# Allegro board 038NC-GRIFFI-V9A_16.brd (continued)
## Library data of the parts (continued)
BC1 BC3 BC5 BC7 BC11 BC13 = 100U-50-E-S-6.6X6.6: Tolerance: TOL; User Part Number: PNXXXXXXXXXX
BC2 BC4 BC6 BC8 BC10 BC12 = 47U-100-E-S10X10-NI: User Part Number: PNXXXXXXXXXX; Tolerance: TOL
BD1 BD2 = BD120-3.5A-S8-LA: User Part Number: PNXXXXXXXXXX; Tolerance: TOL
BR1-BR3 = 560-1-S6: User Part Number: PNXXXXXXXXXX; Tolerance: TOL
BR4 = 1K-1-S6: User Part Number: PNXXXXXXXXXX; Tolerance: TOL
C14 = 1U-16-X5R-S4-YA: User Part Number: PNXXXXXXXXXX; Tolerance: TOL
C84-C86 = 1U-16-X6S-S4-TY: User Part Number: PNXXXXXXXXXX; Tolerance: TOL
C87-C89 UNK1CS1 UNK1CS4 UNK1CS5 UNK1CS19-UNK1CS23 UNK1CS25-UNK1CS28 UNK2CS1 UNK2CS4 UNK2CS5 UNK2CS19-UNK2CS23 UNK2CS25-UNK2CS28 UNK3CS1 UNK3CS4 UNK3CS5 UNK3CS19-UNK3CS23 UNK3CS25-UNK3CS28 UNK4CS1 UNK4CS4 UNK4CS5 UNK4CS19-UNK4CS23 UNK4CS25-UNK4CS28 UNK5CS1 UNK5CS4 UNK5CS5 UNK5CS19-UNK5CS23 UNK5CS25-UNK5CS28 UNK6CS1 UNK6CS4 UNK6CS5 UNK6CS19-UNK6CS23 UNK6CS25-UNK6CS28 UNK7CS1 UNK7CS4 UNK7CS5 UNK7CS19-UNK7CS23 UNK7CS25-UNK7CS28 UNK8CS1 UNK8CS4 UNK8CS5 UNK8CS19-UNK8CS23 UNK8CS25-UNK8CS28 UNK9CS1 UNK9CS4 UNK9CS5 UNK9CS19-UNK9CS23 UNK9CS25-UNK9CS28 UNK10CS1 UNK10CS4 UNK10CS5 UNK10CS19-UNK10CS23 UNK10CS25-UNK10CS28 UNK11CS1 UNK11CS4 UNK11CS5 UNK11CS19-UNK11CS23 UNK11CS25-UNK11CS28 UNK12CS1 UNK12CS4 UNK12CS5 UNK12CS19-UNK12CS23 UNK12CS25-UNK12CS28 UNK13CS1 UNK13CS4 UNK13CS5 UNK13CS19-UNK13CS23 UNK13CS25-UNK13CS28 UNK14CS1 UNK14CS4 UNK14CS5 UNK14CS19-UNK14CS23 UNK14CS25-UNK14CS28 UNK15CS1 UNK15CS4 UNK15CS5 UNK15CS19-UNK15CS23 UNK15CS25-UNK15CS28 UNK16CS1 UNK16CS4 UNK16CS5 UNK16CS19-UNK16CS23 UNK16CS25-UNK16CS28 = 0.1U-10-X7R-S4-MU-1: User Part Number: PNXXXXXXXXXX; Tolerance: TOL
C90 = 100P-50-X8R-S4-KEMET: User Part Number: PNXXXXXXXXXX; Tolerance: TOL
C99-C101 = 10U-35-T-SC: Tolerance: TOL; User Part Number: PNXXXXXXXXXX
C102 C103 = 1U-25-X7R-S6-WA: User Part Number: PNXXXXXXXXXX; Tolerance: TOL
FD1-FD16 REG1_P3V3 REG1_P_5V REG1_P_10V SDUP5V1 SDUP15V1 T_+15V T_-15V T_RLY_5V T_USER_5V T_USER_12V T_USER_-5V TP_EEP_GND TP_EPP_SCLK TP_EPP_SCLK_DGND1 TP_EPP_SDA TP_EPP_SDA_DGND1 TP_EPP_VCC TP_EPP_VCC_DGND1 TP_REG1_P3V3 TP_REG1_P_5V_DGND TP_REG1_P_10V_DGND TP_SDUP5V1 TP_SDUP15V1 TP_USER_GND1 TP_USER_SCLK1 TP_USER_SCLK1_DGND1 TP_USER_SDA1 TP_USER_SDA1_DGND1 UNK1TP_AVSS2/TST UNK1TP_GPIO0-UNK1TP_GPIO4 UNK1TP_LED0-UNK1TP_LED2 UNK1TP_LSIN1_F UNK1TP_LSIN1_G UNK1TP_LSIN1_S UNK1TP_LSIN2/NCHGEN_F UNK1TP_LSIN2/NCHGEN_G UNK1TP_LSIN2/NCHGEN_S UNK1TP_LSOUT1_F UNK1TP_LSOUT1_G UNK1TP_LSOUT1_S UNK1TP_LSOUT2/SUSPEND1_G UNK1TP_LSOUT2/SUSPEND1_S UNK1TP_LSOUT2/SUSPEND_F UNK1TP_NCHG/ATB0_F UNK1TP_NCHG/ATB0_G UNK1TP_NCHG/ATB0_S UNK1TP_NPG/ATB1_F UNK1TP_NPG/ATB1_G UNK1TP_NPG/ATB1_S UNK1TP_NTC UNK1TP_REF_5V UNK1TP_SCL UNK1TP_SDA UNK1TP_SHPHLD_F UNK1TP_SHPHLD_S UNK1TP_SW_F UNK1TP_SW_S UNK1TP_VBAT_F UNK1TP_VBAT_S UNK1TP_VBUS_F UNK1TP_VBUS_S UNK1TP_VDDIO_F UNK1TP_VDDIO_S UNK1TP_VEST UNK1TP_VOUT_F UNK1TP_VOUT_S UNK1TP_VSYS_F UNK1TP_VSYS_S UNK2TP_AVSS2/TST UNK2TP_GPIO0-UNK2TP_GPIO4 UNK2TP_LED0-UNK2TP_LED2 UNK2TP_LSIN1_F UNK2TP_LSIN1_G UNK2TP_LSIN1_S UNK2TP_LSIN2/NCHGEN_F UNK2TP_LSIN2/NCHGEN_G UNK2TP_LSIN2/NCHGEN_S UNK2TP_LSOUT1_F UNK2TP_LSOUT1_G UNK2TP_LSOUT1_S UNK2TP_LSOUT2/SUSPEND1_G UNK2TP_LSOUT2/SUSPEND1_S UNK2TP_LSOUT2/SUSPEND_F UNK2TP_NCHG/ATB0_F UNK2TP_NCHG/ATB0_G UNK2TP_NCHG/ATB0_S UNK2TP_NPG/ATB1_F UNK2TP_NPG/ATB1_G UNK2TP_NPG/ATB1_S UNK2TP_NTC UNK2TP_REF_5V UNK2TP_SCL UNK2TP_SDA UNK2TP_SHPHLD_F UNK2TP_SHPHLD_S UNK2TP_SW_F UNK2TP_SW_S UNK2TP_VBAT_F UNK2TP_VBAT_S UNK2TP_VBUS_F UNK2TP_VBUS_S UNK2TP_VDDIO_F UNK2TP_VDDIO_S UNK2TP_VEST UNK2TP_VOUT_F UNK2TP_VOUT_S UNK2TP_VSYS_F UNK2TP_VSYS_S UNK3TP_AVSS2/TST UNK3TP_GPIO0-UNK3TP_GPIO4 UNK3TP_LED0-UNK3TP_LED2 UNK3TP_LSIN1_F UNK3TP_LSIN1_G UNK3TP_LSIN1_S UNK3TP_LSIN2/NCHGEN_F UNK3TP_LSIN2/NCHGEN_G UNK3TP_LSIN2/NCHGEN_S UNK3TP_LSOUT1_F UNK3TP_LSOUT1_G UNK3TP_LSOUT1_S UNK3TP_LSOUT2/SUSPEND1_G UNK3TP_LSOUT2/SUSPEND1_S UNK3TP_LSOUT2/SUSPEND_F UNK3TP_NCHG/ATB0_F UNK3TP_NCHG/ATB0_G UNK3TP_NCHG/ATB0_S UNK3TP_NPG/ATB1_F UNK3TP_NPG/ATB1_G UNK3TP_NPG/ATB1_S UNK3TP_NTC UNK3TP_REF_5V UNK3TP_SCL UNK3TP_SDA UNK3TP_SHPHLD_F UNK3TP_SHPHLD_S UNK3TP_SW_F UNK3TP_SW_S UNK3TP_VBAT_F UNK3TP_VBAT_S UNK3TP_VBUS_F UNK3TP_VBUS_S UNK3TP_VDDIO_F UNK3TP_VDDIO_S UNK3TP_VEST UNK3TP_VOUT_F UNK3TP_VOUT_S UNK3TP_VSYS_F UNK3TP_VSYS_S UNK4TP_AVSS2/TST UNK4TP_GPIO0-UNK4TP_GPIO4 UNK4TP_LED0-UNK4TP_LED2 UNK4TP_LSIN1_F UNK4TP_LSIN1_G UNK4TP_LSIN1_S UNK4TP_LSIN2/NCHGEN_F UNK4TP_LSIN2/NCHGEN_G UNK4TP_LSIN2/NCHGEN_S UNK4TP_LSOUT1_F UNK4TP_LSOUT1_G UNK4TP_LSOUT1_S UNK4TP_LSOUT2/SUSPEND1_G UNK4TP_LSOUT2/SUSPEND1_S UNK4TP_LSOUT2/SUSPEND_F UNK4TP_NCHG/ATB0_F UNK4TP_NCHG/ATB0_G UNK4TP_NCHG/ATB0_S UNK4TP_NPG/ATB1_F UNK4TP_NPG/ATB1_G UNK4TP_NPG/ATB1_S UNK4TP_NTC UNK4TP_REF_5V UNK4TP_SCL UNK4TP_SDA UNK4TP_SHPHLD_F UNK4TP_SHPHLD_S UNK4TP_SW_F UNK4TP_SW_S UNK4TP_VBAT_F UNK4TP_VBAT_S UNK4TP_VBUS_F UNK4TP_VBUS_S UNK4TP_VDDIO_F UNK4TP_VDDIO_S UNK4TP_VEST UNK4TP_VOUT_F UNK4TP_VOUT_S UNK4TP_VSYS_F UNK4TP_VSYS_S UNK5TP_AVSS2/TST UNK5TP_GPIO0-UNK5TP_GPIO4 UNK5TP_LED0-UNK5TP_LED2 UNK5TP_LSIN1_F UNK5TP_LSIN1_G UNK5TP_LSIN1_S UNK5TP_LSIN2/NCHGEN_F UNK5TP_LSIN2/NCHGEN_G UNK5TP_LSIN2/NCHGEN_S UNK5TP_LSOUT1_F UNK5TP_LSOUT1_G UNK5TP_LSOUT1_S UNK5TP_LSOUT2/SUSPEND1_G UNK5TP_LSOUT2/SUSPEND1_S UNK5TP_LSOUT2/SUSPEND_F UNK5TP_NCHG/ATB0_F UNK5TP_NCHG/ATB0_G UNK5TP_NCHG/ATB0_S UNK5TP_NPG/ATB1_F UNK5TP_NPG/ATB1_G UNK5TP_NPG/ATB1_S UNK5TP_NTC UNK5TP_REF_5V UNK5TP_SCL UNK5TP_SDA UNK5TP_SHPHLD_F UNK5TP_SHPHLD_S UNK5TP_SW_F UNK5TP_SW_S UNK5TP_VBAT_F UNK5TP_VBAT_S UNK5TP_VBUS_F UNK5TP_VBUS_S UNK5TP_VDDIO_F UNK5TP_VDDIO_S UNK5TP_VEST UNK5TP_VOUT_F UNK5TP_VOUT_S UNK5TP_VSYS_F UNK5TP_VSYS_S UNK6TP_AVSS2/TST UNK6TP_GPIO0-UNK6TP_GPIO4 UNK6TP_LED0-UNK6TP_LED2 UNK6TP_LSIN1_F UNK6TP_LSIN1_G UNK6TP_LSIN1_S UNK6TP_LSIN2/NCHGEN_F UNK6TP_LSIN2/NCHGEN_G UNK6TP_LSIN2/NCHGEN_S UNK6TP_LSOUT1_F UNK6TP_LSOUT1_G UNK6TP_LSOUT1_S UNK6TP_LSOUT2/SUSPEND1_G UNK6TP_LSOUT2/SUSPEND1_S UNK6TP_LSOUT2/SUSPEND_F UNK6TP_NCHG/ATB0_F UNK6TP_NCHG/ATB0_G UNK6TP_NCHG/ATB0_S UNK6TP_NPG/ATB1_F UNK6TP_NPG/ATB1_G UNK6TP_NPG/ATB1_S UNK6TP_NTC UNK6TP_REF_5V UNK6TP_SCL UNK6TP_SDA UNK6TP_SHPHLD_F UNK6TP_SHPHLD_S UNK6TP_SW_F UNK6TP_SW_S UNK6TP_VBAT_F UNK6TP_VBAT_S UNK6TP_VBUS_F UNK6TP_VBUS_S UNK6TP_VDDIO_F UNK6TP_VDDIO_S UNK6TP_VEST UNK6TP_VOUT_F UNK6TP_VOUT_S UNK6TP_VSYS_F UNK6TP_VSYS_S UNK7TP_AVSS2/TST UNK7TP_GPIO0-UNK7TP_GPIO4 UNK7TP_LED0-UNK7TP_LED2 UNK7TP_LSIN1_F UNK7TP_LSIN1_G UNK7TP_LSIN1_S UNK7TP_LSIN2/NCHGEN_F UNK7TP_LSIN2/NCHGEN_G UNK7TP_LSIN2/NCHGEN_S UNK7TP_LSOUT1_F UNK7TP_LSOUT1_G UNK7TP_LSOUT1_S UNK7TP_LSOUT2/SUSPEND1_G UNK7TP_LSOUT2/SUSPEND1_S UNK7TP_LSOUT2/SUSPEND_F UNK7TP_NCHG/ATB0_F UNK7TP_NCHG/ATB0_G UNK7TP_NCHG/ATB0_S UNK7TP_NPG/ATB1_F UNK7TP_NPG/ATB1_G UNK7TP_NPG/ATB1_S UNK7TP_NTC UNK7TP_REF_5V UNK7TP_SCL UNK7TP_SDA UNK7TP_SHPHLD_F UNK7TP_SHPHLD_S UNK7TP_SW_F UNK7TP_SW_S UNK7TP_VBAT_F UNK7TP_VBAT_S UNK7TP_VBUS_F UNK7TP_VBUS_S UNK7TP_VDDIO_F UNK7TP_VDDIO_S UNK7TP_VEST UNK7TP_VOUT_F UNK7TP_VOUT_S UNK7TP_VSYS_F UNK7TP_VSYS_S UNK8TP_AVSS2/TST UNK8TP_GPIO0-UNK8TP_GPIO4 UNK8TP_LED0-UNK8TP_LED2 UNK8TP_LSIN1_F UNK8TP_LSIN1_G UNK8TP_LSIN1_S UNK8TP_LSIN2/NCHGEN_F UNK8TP_LSIN2/NCHGEN_G UNK8TP_LSIN2/NCHGEN_S UNK8TP_LSOUT1_F UNK8TP_LSOUT1_G UNK8TP_LSOUT1_S UNK8TP_LSOUT2/SUSPEND1_G UNK8TP_LSOUT2/SUSPEND1_S UNK8TP_LSOUT2/SUSPEND_F UNK8TP_NCHG/ATB0_F UNK8TP_NCHG/ATB0_G UNK8TP_NCHG/ATB0_S UNK8TP_NPG/ATB1_F UNK8TP_NPG/ATB1_G UNK8TP_NPG/ATB1_S UNK8TP_NTC UNK8TP_REF_5V UNK8TP_SCL UNK8TP_SDA UNK8TP_SHPHLD_F UNK8TP_SHPHLD_S UNK8TP_SW_F UNK8TP_SW_S UNK8TP_VBAT_F UNK8TP_VBAT_S UNK8TP_VBUS_F UNK8TP_VBUS_S UNK8TP_VDDIO_F UNK8TP_VDDIO_S UNK8TP_VEST UNK8TP_VOUT_F UNK8TP_VOUT_S UNK8TP_VSYS_F UNK8TP_VSYS_S UNK9TP_AVSS2/TST UNK9TP_GPIO0-UNK9TP_GPIO4 UNK9TP_LED0-UNK9TP_LED2 UNK9TP_LSIN1_F UNK9TP_LSIN1_G UNK9TP_LSIN1_S UNK9TP_LSIN2/NCHGEN_F UNK9TP_LSIN2/NCHGEN_G UNK9TP_LSIN2/NCHGEN_S UNK9TP_LSOUT1_F UNK9TP_LSOUT1_G UNK9TP_LSOUT1_S UNK9TP_LSOUT2/SUSPEND1_G UNK9TP_LSOUT2/SUSPEND1_S UNK9TP_LSOUT2/SUSPEND_F UNK9TP_NCHG/ATB0_F UNK9TP_NCHG/ATB0_G UNK9TP_NCHG/ATB0_S UNK9TP_NPG/ATB1_F UNK9TP_NPG/ATB1_G UNK9TP_NPG/ATB1_S UNK9TP_NTC UNK9TP_REF_5V UNK9TP_SCL UNK9TP_SDA UNK9TP_SHPHLD_F UNK9TP_SHPHLD_S UNK9TP_SW_F UNK9TP_SW_S UNK9TP_VBAT_F UNK9TP_VBAT_S UNK9TP_VBUS_F UNK9TP_VBUS_S UNK9TP_VDDIO_F UNK9TP_VDDIO_S UNK9TP_VEST UNK9TP_VOUT_F UNK9TP_VOUT_S UNK9TP_VSYS_F UNK9TP_VSYS_S UNK10TP_AVSS2/TST UNK10TP_GPIO0-UNK10TP_GPIO4 UNK10TP_LED0-UNK10TP_LED2 UNK10TP_LSIN1_F UNK10TP_LSIN1_G UNK10TP_LSIN1_S UNK10TP_LSIN2/NCHGEN_F UNK10TP_LSIN2/NCHGEN_G UNK10TP_LSIN2/NCHGEN_S UNK10TP_LSOUT1_F UNK10TP_LSOUT1_G UNK10TP_LSOUT1_S UNK10TP_LSOUT2/SUSPEND1_G UNK10TP_LSOUT2/SUSPEND1_S UNK10TP_LSOUT2/SUSPEND_F UNK10TP_NCHG/ATB0_F UNK10TP_NCHG/ATB0_G UNK10TP_NCHG/ATB0_S UNK10TP_NPG/ATB1_F UNK10TP_NPG/ATB1_G UNK10TP_NPG/ATB1_S UNK10TP_NTC UNK10TP_REF_5V UNK10TP_SCL UNK10TP_SDA UNK10TP_SHPHLD_F UNK10TP_SHPHLD_S UNK10TP_SW_F UNK10TP_SW_S UNK10TP_VBAT_F UNK10TP_VBAT_S UNK10TP_VBUS_F UNK10TP_VBUS_S UNK10TP_VDDIO_F UNK10TP_VDDIO_S UNK10TP_VEST UNK10TP_VOUT_F UNK10TP_VOUT_S UNK10TP_VSYS_F UNK10TP_VSYS_S UNK11TP_AVSS2/TST UNK11TP_GPIO0-UNK11TP_GPIO4 UNK11TP_LED0-UNK11TP_LED2 UNK11TP_LSIN1_F UNK11TP_LSIN1_G UNK11TP_LSIN1_S UNK11TP_LSIN2/NCHGEN_F UNK11TP_LSIN2/NCHGEN_G UNK11TP_LSIN2/NCHGEN_S UNK11TP_LSOUT1_F UNK11TP_LSOUT1_G UNK11TP_LSOUT1_S UNK11TP_LSOUT2/SUSPEND1_G UNK11TP_LSOUT2/SUSPEND1_S UNK11TP_LSOUT2/SUSPEND_F UNK11TP_NCHG/ATB0_F UNK11TP_NCHG/ATB0_G UNK11TP_NCHG/ATB0_S UNK11TP_NPG/ATB1_F UNK11TP_NPG/ATB1_G UNK11TP_NPG/ATB1_S UNK11TP_NTC UNK11TP_REF_5V UNK11TP_SCL UNK11TP_SDA UNK11TP_SHPHLD_F UNK11TP_SHPHLD_S UNK11TP_SW_F UNK11TP_SW_S UNK11TP_VBAT_F UNK11TP_VBAT_S UNK11TP_VBUS_F UNK11TP_VBUS_S UNK11TP_VDDIO_F UNK11TP_VDDIO_S UNK11TP_VEST UNK11TP_VOUT_F UNK11TP_VOUT_S UNK11TP_VSYS_F UNK11TP_VSYS_S UNK12TP_AVSS2/TST UNK12TP_GPIO0-UNK12TP_GPIO4 UNK12TP_LED0-UNK12TP_LED2 UNK12TP_LSIN1_F UNK12TP_LSIN1_G UNK12TP_LSIN1_S UNK12TP_LSIN2/NCHGEN_F UNK12TP_LSIN2/NCHGEN_G UNK12TP_LSIN2/NCHGEN_S UNK12TP_LSOUT1_F UNK12TP_LSOUT1_G UNK12TP_LSOUT1_S UNK12TP_LSOUT2/SUSPEND1_G UNK12TP_LSOUT2/SUSPEND1_S UNK12TP_LSOUT2/SUSPEND_F UNK12TP_NCHG/ATB0_F UNK12TP_NCHG/ATB0_G UNK12TP_NCHG/ATB0_S UNK12TP_NPG/ATB1_F UNK12TP_NPG/ATB1_G UNK12TP_NPG/ATB1_S UNK12TP_NTC UNK12TP_REF_5V UNK12TP_SCL UNK12TP_SDA UNK12TP_SHPHLD_F UNK12TP_SHPHLD_S UNK12TP_SW_F UNK12TP_SW_S UNK12TP_VBAT_F UNK12TP_VBAT_S UNK12TP_VBUS_F UNK12TP_VBUS_S UNK12TP_VDDIO_F UNK12TP_VDDIO_S UNK12TP_VEST UNK12TP_VOUT_F UNK12TP_VOUT_S UNK12TP_VSYS_F UNK12TP_VSYS_S UNK13TP_AVSS2/TST UNK13TP_GPIO0-UNK13TP_GPIO4 UNK13TP_LED0-UNK13TP_LED2 UNK13TP_LSIN1_F UNK13TP_LSIN1_G UNK13TP_LSIN1_S UNK13TP_LSIN2/NCHGEN_F UNK13TP_LSIN2/NCHGEN_G UNK13TP_LSIN2/NCHGEN_S UNK13TP_LSOUT1_F UNK13TP_LSOUT1_G UNK13TP_LSOUT1_S UNK13TP_LSOUT2/SUSPEND1_G UNK13TP_LSOUT2/SUSPEND1_S UNK13TP_LSOUT2/SUSPEND_F UNK13TP_NCHG/ATB0_F UNK13TP_NCHG/ATB0_G UNK13TP_NCHG/ATB0_S UNK13TP_NPG/ATB1_F UNK13TP_NPG/ATB1_G UNK13TP_NPG/ATB1_S UNK13TP_NTC UNK13TP_REF_5V UNK13TP_SCL UNK13TP_SDA UNK13TP_SHPHLD_F UNK13TP_SHPHLD_S UNK13TP_SW_F UNK13TP_SW_S UNK13TP_VBAT_F UNK13TP_VBAT_S UNK13TP_VBUS_F UNK13TP_VBUS_S UNK13TP_VDDIO_F UNK13TP_VDDIO_S UNK13TP_VEST UNK13TP_VOUT_F UNK13TP_VOUT_S UNK13TP_VSYS_F UNK13TP_VSYS_S UNK14TP_AVSS2/TST UNK14TP_GPIO0-UNK14TP_GPIO4 UNK14TP_LED0-UNK14TP_LED2 UNK14TP_LSIN1_F UNK14TP_LSIN1_G UNK14TP_LSIN1_S UNK14TP_LSIN2/NCHGEN_F UNK14TP_LSIN2/NCHGEN_G UNK14TP_LSIN2/NCHGEN_S UNK14TP_LSOUT1_F UNK14TP_LSOUT1_G UNK14TP_LSOUT1_S UNK14TP_LSOUT2/SUSPEND1_G UNK14TP_LSOUT2/SUSPEND1_S UNK14TP_LSOUT2/SUSPEND_F UNK14TP_NCHG/ATB0_F UNK14TP_NCHG/ATB0_G UNK14TP_NCHG/ATB0_S UNK14TP_NPG/ATB1_F UNK14TP_NPG/ATB1_G UNK14TP_NPG/ATB1_S UNK14TP_NTC UNK14TP_REF_5V UNK14TP_SCL UNK14TP_SDA UNK14TP_SHPHLD_F UNK14TP_SHPHLD_S UNK14TP_SW_F UNK14TP_SW_S UNK14TP_VBAT_F UNK14TP_VBAT_S UNK14TP_VBUS_F UNK14TP_VBUS_S UNK14TP_VDDIO_F UNK14TP_VDDIO_S UNK14TP_VEST UNK14TP_VOUT_F UNK14TP_VOUT_S UNK14TP_VSYS_F UNK14TP_VSYS_S UNK15TP_AVSS2/TST UNK15TP_GPIO0-UNK15TP_GPIO4 UNK15TP_LED0-UNK15TP_LED2 UNK15TP_LSIN1_F UNK15TP_LSIN1_G UNK15TP_LSIN1_S UNK15TP_LSIN2/NCHGEN_F UNK15TP_LSIN2/NCHGEN_G UNK15TP_LSIN2/NCHGEN_S UNK15TP_LSOUT1_F UNK15TP_LSOUT1_G UNK15TP_LSOUT1_S UNK15TP_LSOUT2/SUSPEND1_G UNK15TP_LSOUT2/SUSPEND1_S UNK15TP_LSOUT2/SUSPEND_F UNK15TP_NCHG/ATB0_F UNK15TP_NCHG/ATB0_G UNK15TP_NCHG/ATB0_S UNK15TP_NPG/ATB1_F UNK15TP_NPG/ATB1_G UNK15TP_NPG/ATB1_S UNK15TP_NTC UNK15TP_REF_5V UNK15TP_SCL UNK15TP_SDA UNK15TP_SHPHLD_F UNK15TP_SHPHLD_S UNK15TP_SW_F UNK15TP_SW_S UNK15TP_VBAT_F UNK15TP_VBAT_S UNK15TP_VBUS_F UNK15TP_VBUS_S UNK15TP_VDDIO_F UNK15TP_VDDIO_S UNK15TP_VEST UNK15TP_VOUT_F UNK15TP_VOUT_S UNK15TP_VSYS_F UNK15TP_VSYS_S UNK16TP_AVSS2/TST UNK16TP_GPIO0-UNK16TP_GPIO4 UNK16TP_LED0-UNK16TP_LED2 UNK16TP_LSIN1_F UNK16TP_LSIN1_G UNK16TP_LSIN1_S UNK16TP_LSIN2/NCHGEN_F UNK16TP_LSIN2/NCHGEN_G UNK16TP_LSIN2/NCHGEN_S UNK16TP_LSOUT1_F UNK16TP_LSOUT1_G UNK16TP_LSOUT1_S UNK16TP_LSOUT2/SUSPEND1_G UNK16TP_LSOUT2/SUSPEND1_S UNK16TP_LSOUT2/SUSPEND_F UNK16TP_NCHG/ATB0_F UNK16TP_NCHG/ATB0_G UNK16TP_NCHG/ATB0_S UNK16TP_NPG/ATB1_F UNK16TP_NPG/ATB1_G UNK16TP_NPG/ATB1_S UNK16TP_NTC UNK16TP_REF_5V UNK16TP_SCL UNK16TP_SDA UNK16TP_SHPHLD_F UNK16TP_SHPHLD_S UNK16TP_SW_F UNK16TP_SW_S UNK16TP_VBAT_F UNK16TP_VBAT_S UNK16TP_VBUS_F UNK16TP_VBUS_S UNK16TP_VDDIO_F UNK16TP_VDDIO_S UNK16TP_VEST UNK16TP_VOUT_F UNK16TP_VOUT_S UNK16TP_VSYS_F UNK16TP_VSYS_S = TP01: Tolerance: TOL; User Part Number: PNXXXXXXXXXX
FUSE1 FUSE2 = 2920L200-2A-S7.98X5.44: User Part Number: PNXXXXXXXXXX; Tolerance: TOL
H1-H4 = M3-HOLE: Tolerance: TOL; User Part Number: PNXXXXXXXXXX
LOGO1 LOGO2 = LOGO_KT_KSMT
M1 = DIAMONDX_X1_OUTLINE_FULL: User Part Number: PNXXXXXXXXXX; Tolerance: TOL
NPM1212-GRIFFI NPM1212-QFN28-P0.4 = REF-CODE-CHIP
R7-R10 = 20K-1-S2: User Part Number: PNXXXXXXXXXX; Tolerance: TOL
R21 = 10K-1-S4: User Part Number: PNXXXXXXXXXX; Tolerance: TOL
R22-R24 = 0-1-S4-YA: User Part Number: PNXXXXXXXXXX; Tolerance: TOL
R376 = 118-1-S2-YA: User Part Number: PNXXXXXXXXXX; Tolerance: TOL
R378 = 365-1-S4: User Part Number: PNXXXXXXXXXX; Tolerance: TOL
R381 = 750-1-S4: User Part Number: PNXXXXXXXXXX; Tolerance: TOL
R382 = 75-1-S4: User Part Number: PNXXXXXXXXXX; Tolerance: TOL
R383 = 121-1-S4: User Part Number: PNXXXXXXXXXX; Tolerance: TOL
RLY_5V1 USER_5V1 USER_12V1 USER_-5V1 = LDG-2-S8: User Part Number: PNXXXXXXXXXX; Tolerance: TOL
SITE1-SITE16 = NPM1212-QFN28-P0.4: Tolerance: TOL; User Part Number: PNXXXXXXXXXX
SLOT0 = DIAMONDX_SLOT0_SDU2: Tolerance: TOL; User Part Number: PNXXXXXXXXXX
SLOT1 SLOT2 SLOT11 SLOT12 = DIAMONDX_X1_DUT_1: Tolerance: TOL; User Part Number: PNXXXXXXXXXX
SLOT3 = DIAMONDX_SLOT3_GX1X: Tolerance: TOL; User Part Number: PNXXXXXXXXXX
SLOT4 = DIAMONDX_SLOT4_GX1X: Tolerance: TOL; User Part Number: PNXXXXXXXXXX
SLOT5 SLOT14-SLOT16 SLOT18 = DIAMONDX_X1_DUT_1: User Part Number: PNXXXXXXXXXX; Tolerance: TOL
SLOT6 = DIAMONDX_SLOT6_PMVIX: Tolerance: TOL; User Part Number: PNXXXXXXXXXX
SLOT7 = DIAMONDX_SLOT7_PMVIX: Tolerance: TOL; User Part Number: PNXXXXXXXXXX
SLOT8 = DIAMONDX_SLOT8_PMVIX: Tolerance: TOL; User Part Number: PNXXXXXXXXXX
SLOT9 = DIAMONDX_SLOT9_PMVIX: Tolerance: TOL; User Part Number: PNXXXXXXXXXX
SLOT10 = DIAMONDX_SLOT10_HDVI: User Part Number: PNXXXXXXXXXX; Tolerance: TOL
SLOT13 = DIAMONDX_SLOT13_HDVI: Tolerance: TOL; User Part Number: PNXXXXXXXXXX
SLOT17 = DIAMONDX_SLOT17_GX1X: Tolerance: TOL; User Part Number: PNXXXXXXXXXX
SLOT19 = DIAMONDX_SLOT19_GX1X: Tolerance: TOL; User Part Number: PNXXXXXXXXXX
U4 = ADT7420UCPZ-LFCSP16: User Part Number: PNXXXXXXXXXX; Tolerance: TOL
U6 = AT24C512C-SSHM-T-SOIC8: User Part Number: PNXXXXXXXXXX; Tolerance: TOL
U44 = ADP151AUJZ-0.2A-33-TSOT23-5: User Part Number: PNXXXXXXXXXX; Tolerance: TOL
U46 U47 = LM1086-1.5A-A-TO263-1: Tolerance: TOL; User Part Number: PNXXXXXXXXXX
UNK0BS1 UNK0BS2 UNK1SH2 UNK1SH7 UNK1SH9 UNK1SH14 UNK1SH16 UNK1SH20 UNK1SH29 UNK1SH30 UNK1SH32-UNK1SH41 UNK2SH2 UNK2SH7 UNK2SH9 UNK2SH14 UNK2SH16 UNK2SH20 UNK2SH29 UNK2SH30 UNK2SH32-UNK2SH41 UNK3SH2 UNK3SH7 UNK3SH9 UNK3SH14 UNK3SH16 UNK3SH20 UNK3SH29 UNK3SH30 UNK3SH32-UNK3SH41 UNK4SH2 UNK4SH7 UNK4SH9 UNK4SH14 UNK4SH16 UNK4SH20 UNK4SH29 UNK4SH30 UNK4SH32-UNK4SH41 UNK5SH2 UNK5SH7 UNK5SH9 UNK5SH14 UNK5SH16 UNK5SH20 UNK5SH29 UNK5SH30 UNK5SH32-UNK5SH41 UNK6SH2 UNK6SH7 UNK6SH9 UNK6SH14 UNK6SH16 UNK6SH20 UNK6SH29 UNK6SH30 UNK6SH32-UNK6SH41 UNK7SH2 UNK7SH7 UNK7SH9 UNK7SH14 UNK7SH16 UNK7SH20 UNK7SH29 UNK7SH30 UNK7SH32-UNK7SH41 UNK8SH2 UNK8SH7 UNK8SH9 UNK8SH14 UNK8SH16 UNK8SH20 UNK8SH29 UNK8SH30 UNK8SH32-UNK8SH41 UNK9SH2 UNK9SH7 UNK9SH9 UNK9SH14 UNK9SH16 UNK9SH20 UNK9SH29 UNK9SH30 UNK9SH32-UNK9SH41 UNK10SH2 UNK10SH7 UNK10SH9 UNK10SH14 UNK10SH16 UNK10SH20 UNK10SH29 UNK10SH30 UNK10SH32-UNK10SH41 UNK11SH2 UNK11SH7 UNK11SH9 UNK11SH14 UNK11SH16 UNK11SH20 UNK11SH29 UNK11SH30 UNK11SH32-UNK11SH41 UNK12SH2 UNK12SH7 UNK12SH9 UNK12SH14 UNK12SH16 UNK12SH20 UNK12SH29 UNK12SH30 UNK12SH32-UNK12SH41 UNK13SH2 UNK13SH7 UNK13SH9 UNK13SH14 UNK13SH16 UNK13SH20 UNK13SH29 UNK13SH30 UNK13SH32-UNK13SH41 UNK14SH2 UNK14SH7 UNK14SH9 UNK14SH14 UNK14SH16 UNK14SH20 UNK14SH29 UNK14SH30 UNK14SH32-UNK14SH41 UNK15SH2 UNK15SH7 UNK15SH9 UNK15SH14 UNK15SH16 UNK15SH20 UNK15SH29 UNK15SH30 UNK15SH32-UNK15SH41 UNK16SH2 UNK16SH7 UNK16SH9 UNK16SH14 UNK16SH16 UNK16SH20 UNK16SH29 UNK16SH30 UNK16SH32-UNK16SH41 = SHORT: User Part Number: PNXXXXXXXXXX; Tolerance: TOL
UNK1C1 UNK2C1 UNK3C1 UNK4C1 UNK5C1 UNK6C1 UNK7C1 UNK8C1 UNK9C1 UNK10C1 UNK11C1 UNK12C1 UNK13C1 UNK14C1 UNK15C1 UNK16C1 = 1U-6.3-X7R-S6-MU: User Part Number: PNXXXXXXXXXX; Tolerance: TOL
UNK1C2 UNK1C4 UNK1C5 UNK1C12 UNK2C2 UNK2C4 UNK2C5 UNK2C12 UNK3C2 UNK3C4 UNK3C5 UNK3C12 UNK4C2 UNK4C4 UNK4C5 UNK4C12 UNK5C2 UNK5C4 UNK5C5 UNK5C12 UNK6C2 UNK6C4 UNK6C5 UNK6C12 UNK7C2 UNK7C4 UNK7C5 UNK7C12 UNK8C2 UNK8C4 UNK8C5 UNK8C12 UNK9C2 UNK9C4 UNK9C5 UNK9C12 UNK10C2 UNK10C4 UNK10C5 UNK10C12 UNK11C2 UNK11C4 UNK11C5 UNK11C12 UNK12C2 UNK12C4 UNK12C5 UNK12C12 UNK13C2 UNK13C4 UNK13C5 UNK13C12 UNK14C2 UNK14C4 UNK14C5 UNK14C12 UNK15C2 UNK15C4 UNK15C5 UNK15C12 UNK16C2 UNK16C4 UNK16C5 UNK16C12 = 2.2U-25-X8R-SA-TDK: User Part Number: PNXXXXXXXXXX; Tolerance: TOL
UNK1C3 UNK2C3 UNK3C3 UNK4C3 UNK5C3 UNK6C3 UNK7C3 UNK8C3 UNK9C3 UNK10C3 UNK11C3 UNK12C3 UNK13C3 UNK14C3 UNK15C3 UNK16C3 = 10U-6.3-X7R-S6-SS: User Part Number: PNXXXXXXXXXX; Tolerance: TOL
UNK1C6 UNK2C6 UNK3C6 UNK4C6 UNK5C6 UNK6C6 UNK7C6 UNK8C6 UNK9C6 UNK10C6 UNK11C6 UNK12C6 UNK13C6 UNK14C6 UNK15C6 UNK16C6 = 4.7U-6.3-X-S6: User Part Number: PNXXXXXXXXXX; Tolerance: TOL
UNK1C7 UNK1C9 UNK2C7 UNK2C9 UNK3C7 UNK3C9 UNK4C7 UNK4C9 UNK5C7 UNK5C9 UNK6C7 UNK6C9 UNK7C7 UNK7C9 UNK8C7 UNK8C9 UNK9C7 UNK9C9 UNK10C7 UNK10C9 UNK11C7 UNK11C9 UNK12C7 UNK12C9 UNK13C7 UNK13C9 UNK14C7 UNK14C9 UNK15C7 UNK15C9 UNK16C7 UNK16C9 = 0.1U-25-X7R-S6-YA: User Part Number: PNXXXXXXXXXX; Tolerance: TOL
UNK1C8 UNK2C8 UNK3C8 UNK4C8 UNK5C8 UNK6C8 UNK7C8 UNK8C8 UNK9C8 UNK10C8 UNK11C8 UNK12C8 UNK13C8 UNK14C8 UNK15C8 UNK16C8 = 1U-50-X7R-S6-TY: User Part Number: PNXXXXXXXXXX; Tolerance: TOL
UNK1K1-UNK1K14 UNK2K1-UNK2K14 UNK3K1-UNK3K14 UNK4K1-UNK4K14 UNK5K1-UNK5K14 UNK6K1-UNK6K14 UNK7K1-UNK7K14 UNK8K1-UNK8K14 UNK9K1-UNK9K14 UNK10K1-UNK10K14 UNK11K1-UNK11K14 UNK12K1-UNK12K14 UNK13K1-UNK13K14 UNK14K1-UNK14K14 UNK15K1-UNK15K14 UNK16K1-UNK16K14 = UA2-12NJ-V2: Tolerance: TOL; User Part Number: PNXXXXXXXXXX
UNK1R1 UNK2R1 UNK3R1 UNK4R1 UNK5R1 UNK6R1 UNK7R1 UNK8R1 UNK9R1 UNK10R1 UNK11R1 UNK12R1 UNK13R1 UNK14R1 UNK15R1 UNK16R1 = 4.7K-1-S4-WA: User Part Number: PNXXXXXXXXXX; Tolerance: TOL
UNK1R2 UNK2R2 UNK3R2 UNK4R2 UNK5R2 UNK6R2 UNK7R2 UNK8R2 UNK9R2 UNK10R2 UNK11R2 UNK12R2 UNK13R2 UNK14R2 UNK15R2 UNK16R2 = 3.01K-0.1-S4-PAN: User Part Number: PNXXXXXXXXXX; Tolerance: TOL
UNK1R3 UNK2R3 UNK3R3 UNK4R3 UNK5R3 UNK6R3 UNK7R3 UNK8R3 UNK9R3 UNK10R3 UNK11R3 UNK12R3 UNK13R3 UNK14R3 UNK15R3 UNK16R3 = 10K-0.1-S4: User Part Number: PNXXXXXXXXXX; Tolerance: TOL
UNK1R7 UNK1R8 UNK2R7 UNK2R8 UNK3R7 UNK3R8 UNK4R7 UNK4R8 UNK5R7 UNK5R8 UNK6R7 UNK6R8 UNK7R7 UNK7R8 UNK8R7 UNK8R8 UNK9R7 UNK9R8 UNK10R7 UNK10R8 UNK11R7 UNK11R8 UNK12R7 UNK12R8 UNK13R7 UNK13R8 UNK14R7 UNK14R8 UNK15R7 UNK15R8 UNK16R7 UNK16R8 = 1K-1-S4: User Part Number: PNXXXXXXXXXX; Tolerance: TOL
UNK1R13 UNK1R14 UNK1RS1-UNK1RS5 UNK2R13 UNK2R14 UNK2RS1-UNK2RS5 UNK3R13 UNK3R14 UNK3RS1-UNK3RS5 UNK4R13 UNK4R14 UNK4RS1-UNK4RS5 UNK5R13 UNK5R14 UNK5RS1-UNK5RS5 UNK6R13 UNK6R14 UNK6RS1-UNK6RS5 UNK7R13 UNK7R14 UNK7RS1-UNK7RS5 UNK8R13 UNK8R14 UNK8RS1-UNK8RS5 UNK9R13 UNK9R14 UNK9RS1-UNK9RS5 UNK10R13 UNK10R14 UNK10RS1-UNK10RS5 UNK11R13 UNK11R14 UNK11RS1-UNK11RS5 UNK12R13 UNK12R14 UNK12RS1-UNK12RS5 UNK13R13 UNK13R14 UNK13RS1-UNK13RS5 UNK14R13 UNK14R14 UNK14RS1-UNK14RS5 UNK15R13 UNK15R14 UNK15RS1-UNK15RS5 UNK16R13 UNK16R14 UNK16RS1-UNK16RS5 = 0-5-S4: User Part Number: PNXXXXXXXXXX; Tolerance: TOL
UNK1R41 UNK2R41 UNK3R41 UNK4R41 UNK5R41 UNK6R41 UNK7R41 UNK8R41 UNK9R41 UNK10R41 UNK11R41 UNK12R41 UNK13R41 UNK14R41 UNK15R41 UNK16R41 = 24K-0.1-S4: User Part Number: PNXXXXXXXXXX; Tolerance: TOL
UNK1R42 UNK2R42 UNK3R42 UNK4R42 UNK5R42 UNK6R42 UNK7R42 UNK8R42 UNK9R42 UNK10R42 UNK11R42 UNK12R42 UNK13R42 UNK14R42 UNK15R42 UNK16R42 = 44.2K-0.1-S4-PAN: User Part Number: PNXXXXXXXXXX; Tolerance: TOL
UNK1U1 UNK2U1 UNK3U1 UNK4U1 UNK5U1 UNK6U1 UNK7U1 UNK8U1 UNK9U1 UNK10U1 UNK11U1 UNK12U1 UNK13U1 UNK14U1 UNK15U1 UNK16U1 = ADR4550BRZ-SOIC8: Tolerance: TOL; User Part Number: PNXXXXXXXXXX
UNK038NC-GRIFFI18R-A100 UNK980NC-GRIFFI-1C4 = REF-CODE-PCB
UNK730-03146-001_FP-ATE = REF-CODE-SOCKET
UNK* UNK*#2 = -: Tolerance: TOL; User Part Number: PNXXXXXXXXXX

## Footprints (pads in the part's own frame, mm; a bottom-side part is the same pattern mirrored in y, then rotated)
C0402
  custom 0.15x0.15 smd: 1(-0.5,0) 2(0.5,0)
C0603
  rect 0.889x0.889 smd: 1(-0.85,0) 2(0.85,0)
C1206
  rect 1.321x1.829 smd: 1(-1.25,0) 2(1.25,0)
CHIP_CODE
  round 0.051 smd: 1(0,0)
CODE_C
  rect 2.286x2.54 smd: 1(-2.54,0) 2(2.54,0)
DEFAULT_SHORT_SMALL
  custom 0.07x0.07 smd: 1(-0.5,0) 2(0.5,0)
EC_6P3X7P7MM_S
  rect 1.016x3.556 smd: 1(0,2.78) 2(0,-2.78)
ECS_10X10MM_H10P5
  rect 1.27x3.81 smd: 1(0,4.155) 2(0,-4.155)
FB0805
  rect 1.118x1.372 smd: 1(-0.965,0) 2(0.965,0)
FD_040_V2
  round 1.016 smd: 1(0,0)
FUSE_2920_H45
  rect 2.337x5.639 smd: 1(-3.7,0) 2(3.7,0)
LED_0805
  rect 1.118x1.372 smd: 1(0.95,0) 2(-0.95,0)
LFCSP16_0P65MM_G
  rect 0.914x0.305 smd: 1(-2.05,0.975) 2(-2.05,0.325) 3(-2.05,-0.325) 4(-2.05,-0.975) 9(2.05,-0.975) 10(2.05,-0.325) 11(2.05,0.325) 12(2.05,0.975)
  rect 0.305x0.914 smd: 5(-0.975,-2.05) 6(-0.325,-2.05) 7(0.325,-2.05) 8(0.975,-2.05) 13(0.975,2.05) 14(0.325,2.05) 15(-0.325,2.05) 16(-0.975,2.05)
  rect 2.7x2.7 smd: 17(0,0)
LOGO_KT_KSMT
  round 0.051 smd: 1(-0.711,-0.711)
LOGO_NC_NORDIC
  round 0.051 smd: 1(-0.711,-0.711)
M3_NPTH169
  round 0.508 hole 4.293 unplated: (0,0)
PCB_CODE
  round 0.051 smd: 1(0,0)
PG_LTXDX_F_X1_GX1_SL17_V2
  round 0.508 hole 3.2 unplated: (83.466,154.842)
  round 0.051 hole 2.489x2.21 unplated: (84.465,220.342)
  rect 1.016x1.016 smd: A1(78.836,218.796)
  round 1.016 hole 0.559: A2(77.711,217.796) A3(78.836,216.796) A4(77.711,215.796) A5(78.836,214.796) A6(77.711,213.796) A7(78.836,212.796) A8(77.711,211.796) A9(78.836,210.796) A10(77.711,209.796) A11(78.836,208.796) A12(77.711,207.796) A13(78.836,206.796) A14(77.711,205.796) A15(78.836,204.796) A16(77.711,203.796) A17(78.836,202.796) A18(77.711,201.796) A19(78.836,200.796) A20(77.711,199.796) A21(78.836,198.796) A22(77.711,197.796) A23(78.836,196.796) A24(77.711,195.796) A25(78.836,194.796) A26(77.711,193.796) A27(78.836,192.796) A28(77.711,191.796) A29(78.836,190.796) A30(77.711,189.796) A31(78.836,188.796) A32(77.711,187.796) A33(78.836,186.796) A34(77.711,185.796) A35(78.836,184.796) A36(77.711,183.796) A37(78.836,182.796) A38(77.711,181.796) A39(78.836,180.796) A40(77.711,179.796) A41(78.836,178.796) A42(77.711,177.796) A43(78.836,176.796) A44(77.711,175.796) A45(78.836,174.796) A46(77.711,173.796) A47(78.836,172.796) A48(77.711,171.796) A49(78.836,170.796) A50(77.711,169.796) A51(78.836,168.796) A52(77.711,167.796) A53(78.836,166.796) A54(77.711,165.796) A55(78.836,164.796) A56(77.711,163.796) A57(78.836,162.796) A58(77.711,161.796) A59(78.836,160.796) A60(77.711,159.796) A61(78.836,158.796) B2(79.96,217.796) B3(81.085,216.796) B4(79.96,215.796) B5(81.085,214.796) B6(79.96,213.796) B7(81.085,212.796) B8(79.96,211.796) B9(81.085,210.796) B10(79.96,209.796) B11(81.085,208.796) B12(79.96,207.796) B13(81.085,206.796) B14(79.96,205.796) B15(81.085,204.796) B16(79.96,203.796) B17(81.085,202.796) B18(79.96,201.796) B19(81.085,200.796) B20(79.96,199.796) B21(81.085,198.796) B22(79.96,197.796) B23(81.085,196.796) B24(79.96,195.796) B25(81.085,194.796) B26(79.96,193.796) B27(81.085,192.796) B28(79.96,191.796) B29(81.085,190.796) B30(79.96,189.796) B31(81.085,188.796) B32(79.96,187.796) B33(81.085,186.796) B34(79.96,185.796) B35(81.085,184.796) B36(79.96,183.796) B37(81.085,182.796) B38(79.96,181.796) B39(81.085,180.796) B40(79.96,179.796) B41(81.085,178.796) B42(79.96,177.796) B43(81.085,176.796) B44(79.96,175.796) B45(81.085,174.796) B46(79.96,173.796) B47(81.085,172.796) B48(79.96,171.796) B49(81.085,170.796) B50(79.96,169.796) B51(81.085,168.796) B52(79.96,167.796) B53(81.085,166.796) B54(79.96,165.796) B55(81.085,164.796) B56(79.96,163.796) B57(81.085,162.796) B58(79.96,161.796) B59(81.085,160.796) B60(79.96,159.796) B61(81.085,158.796) C2(82.21,217.796) C3(83.336,216.796) C4(82.21,215.796) C5(83.336,214.796) C6(82.21,213.796) C7(83.336,212.796) C8(82.21,211.796) C9(83.336,210.796) C10(82.21,209.796) C11(83.336,208.796) C12(82.21,207.796) C13(83.336,206.796) C14(82.21,205.796) C15(83.336,204.796) C16(82.21,203.796) C17(83.336,202.796) C18(82.21,201.796) C19(83.336,200.796) C20(82.21,199.796) C21(83.336,198.796) C22(82.21,197.796) C23(83.336,196.796) C24(82.21,195.796) C25(83.336,194.796) C26(82.21,193.796) C27(83.336,192.796) C28(82.21,191.796) C29(83.336,190.796) C30(82.21,189.796) C31(83.336,188.796) C32(82.21,187.796) C33(83.336,186.796) C34(82.21,185.796) C35(83.336,184.796) C36(82.21,183.796) C37(83.336,182.796) C38(82.21,181.796) C39(83.336,180.796) C40(82.21,179.796) C41(83.336,178.796) C42(82.21,177.796) C43(83.336,176.796) C44(82.21,175.796) C45(83.336,174.796) C46(82.21,173.796) C47(83.336,172.796) C48(82.21,171.796) C49(83.336,170.796) C50(82.21,169.796) C51(83.336,168.796) C52(82.21,167.796) C53(83.336,166.796) C54(82.21,165.796) C55(83.336,164.796) C56(82.21,163.796) C57(83.336,162.796) C58(82.21,161.796) C59(83.336,160.796) C60(82.21,159.796) C61(83.336,158.796) D2(84.461,217.796) D3(85.586,216.796) D4(84.461,215.796) D5(85.586,214.796) D6(84.461,213.796) D7(85.586,212.796) D8(84.461,211.796) D9(85.586,210.796) D10(84.461,209.796) D11(85.586,208.796) D12(84.461,207.796) D13(85.586,206.796) D14(84.461,205.796) D15(85.586,204.796) D16(84.461,203.796) D17(85.586,202.796) D18(84.461,201.796) D19(85.586,200.796) D20(84.461,199.796) D21(85.586,198.796) D22(84.461,197.796) D23(85.586,196.796) D24(84.461,195.796) D25(85.586,194.796) D26(84.461,193.796) D27(85.586,192.796) D28(84.461,191.796) D29(85.586,190.796) D30(84.461,189.796) D31(85.586,188.796) D32(84.461,187.796) D33(85.586,186.796) D34(84.461,185.796) D35(85.586,184.796) D36(84.461,183.796) D37(85.586,182.796) D38(84.461,181.796) D39(85.586,180.796) D40(84.461,179.796) D41(85.586,178.796) D42(84.461,177.796) D43(85.586,176.796) D44(84.461,175.796) D45(85.586,174.796) D46(84.461,173.796) D47(85.586,172.796) D48(84.461,171.796) D49(85.586,170.796) D50(84.461,169.796) D51(85.586,168.796) D52(84.461,167.796) D53(85.586,166.796) D54(84.461,165.796) D55(85.586,164.796) D56(84.461,163.796) D57(85.586,162.796) D58(84.461,161.796) D59(85.586,160.796) D60(84.461,159.796) D61(85.586,158.796) E2(86.711,217.796) E3(87.835,216.796) E4(86.711,215.796) E5(87.835,214.796) E6(86.711,213.796) E7(87.835,212.796) E8(86.711,211.796) E9(87.835,210.796) E10(86.711,209.796) E11(87.835,208.796) E12(86.711,207.796) E13(87.835,206.796) E14(86.711,205.796) E15(87.835,204.796) E16(86.711,203.796) E17(87.835,202.796) E18(86.711,201.796) E19(87.835,200.796) E20(86.711,199.796) E21(87.835,198.796) E22(86.711,197.796) E23(87.835,196.796) E24(86.711,195.796) E25(87.835,194.796) E26(86.711,193.796) E27(87.835,192.796) E28(86.711,191.796) E29(87.835,190.796) E30(86.711,189.796) E31(87.835,188.796) E32(86.711,187.796) E33(87.835,186.796) E34(86.711,185.796) E35(87.835,184.796) E36(86.711,183.796) E37(87.835,182.796) E38(86.711,181.796) E39(87.835,180.796) E40(86.711,179.796) E41(87.835,178.796) E42(86.711,177.796) E43(87.835,176.796) E44(86.711,175.796) E45(87.835,174.796) E46(86.711,173.796) E47(87.835,172.796) E48(86.711,171.796) E49(87.835,170.796) E50(86.711,169.796) E51(87.835,168.796) E52(86.711,167.796) E53(87.835,166.796) E54(86.711,165.796) E55(87.835,164.796) E56(86.711,163.796) E57(87.835,162.796) E58(86.711,161.796) E59(87.835,160.796) E60(86.711,159.796) E61(87.835,158.796) F2(88.96,217.796) F3(90.085,216.796) F4(88.96,215.796) F5(90.085,214.796) F6(88.96,213.796) F7(90.085,212.796) F8(88.96,211.796) F9(90.085,210.796) F10(88.96,209.796) F11(90.085,208.796) F12(88.96,207.796) F13(90.085,206.796) F14(88.96,205.796) F15(90.085,204.796) F16(88.96,203.796) F17(90.085,202.796) F18(88.96,201.796) F19(90.085,200.796) F20(88.96,199.796) F21(90.085,198.796) F22(88.96,197.796) F23(90.085,196.796) F24(88.96,195.796) F25(90.085,194.796) F26(88.96,193.796) F27(90.085,192.796) F28(88.96,191.796) F29(90.085,190.796) F30(88.96,189.796) F31(90.085,188.796) F32(88.96,187.796) F33(90.085,186.796) F34(88.96,185.796) F35(90.085,184.796) F36(88.96,183.796) F37(90.085,182.796) F38(88.96,181.796) F39(90.085,180.796) F40(88.96,179.796) F41(90.085,178.796) F42(88.96,177.796) F43(90.085,176.796) F44(88.96,175.796) F45(90.085,174.796) F46(88.96,173.796) F47(90.085,172.796) F48(88.96,171.796) F49(90.085,170.796) F50(88.96,169.796) F51(90.085,168.796) F52(88.96,167.796) F53(90.085,166.796) F54(88.96,165.796) F55(90.085,164.796) F56(88.96,163.796) F57(90.085,162.796) F58(88.96,161.796) F59(90.085,160.796) F60(88.96,159.796) F61(90.085,158.796) G2(91.21,217.796) G4(91.21,215.796) G6(91.21,213.796) G8(91.21,211.796) G10(91.21,209.796) G12(91.21,207.796) G14(91.21,205.796) G16(91.21,203.796) G18(91.21,201.796) G20(91.21,199.796) G22(91.21,197.796) G24(91.21,195.796) G26(91.21,193.796) G28(91.21,191.796) G30(91.21,189.796) G32(91.21,187.796) G34(91.21,185.796) G36(91.21,183.796) G38(91.21,181.796) G40(91.21,179.796) Z5(76.586,214.796) Z7(76.586,212.796) Z9(76.586,210.796) Z11(76.586,208.796) Z13(76.586,206.796) Z15(76.586,204.796) Z17(76.586,202.796) Z19(76.586,200.796) Z21(76.586,198.796) Z23(76.586,196.796) Z25(76.586,194.796) Z27(76.586,192.796) Z29(76.586,190.796) Z31(76.586,188.796) Z33(76.586,186.796) Z35(76.586,184.796) Z37(76.586,182.796) Z39(76.586,180.796) Z41(76.586,178.796) Z43(76.586,176.796) Z45(76.586,174.796) Z47(76.586,172.796) Z49(76.586,170.796) Z51(76.586,168.796) Z53(76.586,166.796) Z55(76.586,164.796) Z57(76.586,162.796) Z59(76.586,160.796) Z61(76.586,158.796)
  round 1.016 smd: B1(81.085,218.796) B62(79.96,157.796) C1(83.336,218.796) C62(82.21,157.796) D1(85.586,218.796) E1(87.835,218.796) E62(86.711,157.796) F1(90.085,218.796) F62(88.96,157.796) G42(91.21,177.796) G44(91.21,175.796) G46(91.21,173.796) G48(91.21,171.796) G50(91.21,169.796) G52(91.21,167.796) G54(91.21,165.796) G56(91.21,163.796) G58(91.21,161.796) G60(91.21,159.796)
PG_LTXDX_F_X1_GX1_SL19_V2
  round 0.508 hole 3.2 unplated: (107.596,154.842)
  round 0.051 hole 2.489x2.21 unplated: (108.595,220.342)
  rect 1.016x1.016 smd: A1(102.966,218.796)
  round 1.016 hole 0.559: A2(101.841,217.796) A3(102.966,216.796) A4(101.841,215.796) A5(102.966,214.796) A6(101.841,213.796) A7(102.966,212.796) A8(101.841,211.796) A9(102.966,210.796) A10(101.841,209.796) A11(102.966,208.796) A12(101.841,207.796) A13(102.966,206.796) A14(101.841,205.796) A15(102.966,204.796) A16(101.841,203.796) A17(102.966,202.796) A18(101.841,201.796) A19(102.966,200.796) A20(101.841,199.796) A21(102.966,198.796) A22(101.841,197.796) A23(102.966,196.796) A24(101.841,195.796) A25(102.966,194.796) A26(101.841,193.796) A27(102.966,192.796) A28(101.841,191.796) A29(102.966,190.796) A30(101.841,189.796) A31(102.966,188.796) A32(101.841,187.796) A33(102.966,186.796) A34(101.841,185.796) A35(102.966,184.796) A36(101.841,183.796) A37(102.966,182.796) A38(101.841,181.796) A39(102.966,180.796) A40(101.841,179.796) A41(102.966,178.796) A42(101.841,177.796) A43(102.966,176.796) A44(101.841,175.796) A45(102.966,174.796) A46(101.841,173.796) A47(102.966,172.796) A48(101.841,171.796) A49(102.966,170.796) A50(101.841,169.796) A51(102.966,168.796) A52(101.841,167.796) A53(102.966,166.796) A54(101.841,165.796) A55(102.966,164.796) A56(101.841,163.796) A57(102.966,162.796) A58(101.841,161.796) A59(102.966,160.796) A60(101.841,159.796) A61(102.966,158.796) B2(104.09,217.796) B3(105.215,216.796) B4(104.09,215.796) B5(105.215,214.796) B6(104.09,213.796) B7(105.215,212.796) B8(104.09,211.796) B9(105.215,210.796) B10(104.09,209.796) B11(105.215,208.796) B12(104.09,207.796) B13(105.215,206.796) B14(104.09,205.796) B15(105.215,204.796) B16(104.09,203.796) B17(105.215,202.796) B18(104.09,201.796) B19(105.215,200.796) B20(104.09,199.796) B21(105.215,198.796) B22(104.09,197.796) B23(105.215,196.796) B24(104.09,195.796) B25(105.215,194.796) B26(104.09,193.796) B27(105.215,192.796) B28(104.09,191.796) B29(105.215,190.796) B30(104.09,189.796) B31(105.215,188.796) B32(104.09,187.796) B33(105.215,186.796) B34(104.09,185.796) B35(105.215,184.796) B36(104.09,183.796) B37(105.215,182.796) B38(104.09,181.796) B39(105.215,180.796) B40(104.09,179.796) B41(105.215,178.796) B42(104.09,177.796) B43(105.215,176.796) B44(104.09,175.796) B45(105.215,174.796) B46(104.09,173.796) B47(105.215,172.796) B48(104.09,171.796) B49(105.215,170.796) B50(104.09,169.796) B51(105.215,168.796) B52(104.09,167.796) B53(105.215,166.796) B54(104.09,165.796) B55(105.215,164.796) B56(104.09,163.796) B57(105.215,162.796) B58(104.09,161.796) B59(105.215,160.796) B60(104.09,159.796) B61(105.215,158.796) C2(106.34,217.796) C3(107.466,216.796) C4(106.34,215.796) C5(107.466,214.796) C6(106.34,213.796) C7(107.466,212.796) C8(106.34,211.796) C9(107.466,210.796) C10(106.34,209.796) C11(107.466,208.796) C12(106.34,207.796) C13(107.466,206.796) C14(106.34,205.796) C15(107.466,204.796) C16(106.34,203.796) C17(107.466,202.796) C18(106.34,201.796) C19(107.466,200.796) C20(106.34,199.796) C21(107.466,198.796) C22(106.34,197.796) C23(107.466,196.796) C24(106.34,195.796) C25(107.466,194.796) C26(106.34,193.796) C27(107.466,192.796) C28(106.34,191.796) C29(107.466,190.796) C30(106.34,189.796) C31(107.466,188.796) C32(106.34,187.796) C33(107.466,186.796) C34(106.34,185.796) C35(107.466,184.796) C36(106.34,183.796) C37(107.466,182.796) C38(106.34,181.796) C39(107.466,180.796) C40(106.34,179.796) C41(107.466,178.796) C42(106.34,177.796) C43(107.466,176.796) C44(106.34,175.796) C45(107.466,174.796) C46(106.34,173.796) C47(107.466,172.796) C48(106.34,171.796) C49(107.466,170.796) C50(106.34,169.796) C51(107.466,168.796) C52(106.34,167.796) C53(107.466,166.796) C54(106.34,165.796) C55(107.466,164.796) C56(106.34,163.796) C57(107.466,162.796) C58(106.34,161.796) C59(107.466,160.796) C60(106.34,159.796) C61(107.466,158.796) D2(108.591,217.796) D3(109.716,216.796) D4(108.591,215.796) D5(109.716,214.796) D6(108.591,213.796) D7(109.716,212.796) D8(108.591,211.796) D9(109.716,210.796) D10(108.591,209.796) D11(109.716,208.796) D12(108.591,207.796) D13(109.716,206.796) D14(108.591,205.796) D15(109.716,204.796) D16(108.591,203.796) D17(109.716,202.796) D18(108.591,201.796) D19(109.716,200.796) D20(108.591,199.796) D21(109.716,198.796) D22(108.591,197.796) D23(109.716,196.796) D24(108.591,195.796) D25(109.716,194.796) D26(108.591,193.796) D27(109.716,192.796) D28(108.591,191.796) D29(109.716,190.796) D30(108.591,189.796) D31(109.716,188.796) D32(108.591,187.796) D33(109.716,186.796) D34(108.591,185.796) D35(109.716,184.796) D36(108.591,183.796) D37(109.716,182.796) D38(108.591,181.796) D39(109.716,180.796) D40(108.591,179.796) D41(109.716,178.796) D42(108.591,177.796) D43(109.716,176.796) D44(108.591,175.796) D45(109.716,174.796) D46(108.591,173.796) D47(109.716,172.796) D48(108.591,171.796) D49(109.716,170.796) D50(108.591,169.796) D51(109.716,168.796) D52(108.591,167.796) D53(109.716,166.796) D54(108.591,165.796) D55(109.716,164.796) D56(108.591,163.796) D57(109.716,162.796) D58(108.591,161.796) D59(109.716,160.796) D60(108.591,159.796) D61(109.716,158.796) E2(110.841,217.796) E3(111.965,216.796) E4(110.841,215.796) E5(111.965,214.796) E6(110.841,213.796) E7(111.965,212.796) E8(110.841,211.796) E9(111.965,210.796) E10(110.841,209.796) E11(111.965,208.796) E12(110.841,207.796) E13(111.965,206.796) E14(110.841,205.796) E15(111.965,204.796) E16(110.841,203.796) E17(111.965,202.796) E18(110.841,201.796) E19(111.965,200.796) E20(110.841,199.796) E21(111.965,198.796) E22(110.841,197.796) E23(111.965,196.796) E24(110.841,195.796) E25(111.965,194.796) E26(110.841,193.796) E27(111.965,192.796) E28(110.841,191.796) E29(111.965,190.796) E30(110.841,189.796) E31(111.965,188.796) E32(110.841,187.796) E33(111.965,186.796) E34(110.841,185.796) E35(111.965,184.796) E36(110.841,183.796) E37(111.965,182.796) E38(110.841,181.796) E39(111.965,180.796) E40(110.841,179.796) E41(111.965,178.796) E42(110.841,177.796) E43(111.965,176.796) E44(110.841,175.796) E45(111.965,174.796) E46(110.841,173.796) E47(111.965,172.796) E48(110.841,171.796) E49(111.965,170.796) E50(110.841,169.796) E51(111.965,168.796) E52(110.841,167.796) E53(111.965,166.796) E54(110.841,165.796) E55(111.965,164.796) E56(110.841,163.796) E57(111.965,162.796) E58(110.841,161.796) E59(111.965,160.796) E60(110.841,159.796) E61(111.965,158.796) F2(113.09,217.796) F3(114.215,216.796) F4(113.09,215.796) F5(114.215,214.796) F6(113.09,213.796) F7(114.215,212.796) F8(113.09,211.796) F9(114.215,210.796) F10(113.09,209.796) F11(114.215,208.796) F12(113.09,207.796) F13(114.215,206.796) F14(113.09,205.796) F15(114.215,204.796) F16(113.09,203.796) F17(114.215,202.796) F18(113.09,201.796) F19(114.215,200.796) F20(113.09,199.796) F21(114.215,198.796) F22(113.09,197.796) F23(114.215,196.796) F24(113.09,195.796) F25(114.215,194.796) F26(113.09,193.796) F27(114.215,192.796) F28(113.09,191.796) F29(114.215,190.796) F30(113.09,189.796) F31(114.215,188.796) F32(113.09,187.796) F33(114.215,186.796) F34(113.09,185.796) F35(114.215,184.796) F36(113.09,183.796) F37(114.215,182.796) F38(113.09,181.796) F39(114.215,180.796) F40(113.09,179.796) F41(114.215,178.796) F42(113.09,177.796) F43(114.215,176.796) F44(113.09,175.796) F45(114.215,174.796) F46(113.09,173.796) F47(114.215,172.796) F48(113.09,171.796) F49(114.215,170.796) F50(113.09,169.796) F51(114.215,168.796) F52(113.09,167.796) F53(114.215,166.796) F54(113.09,165.796) F55(114.215,164.796) F56(113.09,163.796) F57(114.215,162.796) F58(113.09,161.796) F59(114.215,160.796) F60(113.09,159.796) F61(114.215,158.796) G2(115.34,217.796) G4(115.34,215.796) G6(115.34,213.796) G8(115.34,211.796) G10(115.34,209.796) G12(115.34,207.796) G14(115.34,205.796) G16(115.34,203.796) G18(115.34,201.796) G20(115.34,199.796) G22(115.34,197.796) G24(115.34,195.796) G26(115.34,193.796) G28(115.34,191.796) G30(115.34,189.796) G32(115.34,187.796) G34(115.34,185.796) G36(115.34,183.796) G38(115.34,181.796) G40(115.34,179.796) Z5(100.716,214.796) Z7(100.716,212.796) Z9(100.716,210.796) Z11(100.716,208.796) Z13(100.716,206.796) Z15(100.716,204.796) Z17(100.716,202.796) Z19(100.716,200.796) Z21(100.716,198.796) Z23(100.716,196.796) Z25(100.716,194.796) Z27(100.716,192.796) Z29(100.716,190.796) Z31(100.716,188.796) Z33(100.716,186.796) Z35(100.716,184.796) Z37(100.716,182.796) Z39(100.716,180.796) Z41(100.716,178.796) Z43(100.716,176.796) Z45(100.716,174.796) Z47(100.716,172.796) Z49(100.716,170.796) Z51(100.716,168.796) Z53(100.716,166.796) Z55(100.716,164.796) Z57(100.716,162.796) Z59(100.716,160.796) Z61(100.716,158.796)
  round 1.016 smd: B1(105.215,218.796) B62(104.09,157.796) C1(107.466,218.796) C62(106.34,157.796) D1(109.716,218.796) E1(111.965,218.796) E62(110.841,157.796) F1(114.215,218.796) F62(113.09,157.796) G42(115.34,177.796) G44(115.34,175.796) G46(115.34,173.796) G48(115.34,171.796) G50(115.34,169.796) G52(115.34,167.796) G54(115.34,165.796) G56(115.34,163.796) G58(115.34,161.796) G60(115.34,159.796)
PG_LTXDX_F_X1_GX1X_SL03_V2
  round 0.508 hole 3.2 unplated: (-85.444,154.842)
  round 0.051 hole 2.489x2.21 unplated: (-84.445,220.342)
  rect 1.016x1.016 smd: A1(-90.074,218.796)
  round 1.016 hole 0.559: A2(-91.199,217.796) A3(-90.074,216.796) A4(-91.199,215.796) A5(-90.074,214.796) A6(-91.199,213.796) A7(-90.074,212.796) A8(-91.199,211.796) A9(-90.074,210.796) A10(-91.199,209.796) A11(-90.074,208.796) A12(-91.199,207.796) A13(-90.074,206.796) A14(-91.199,205.796) A15(-90.074,204.796) A16(-91.199,203.796) A17(-90.074,202.796) A18(-91.199,201.796) A19(-90.074,200.796) A20(-91.199,199.796) A21(-90.074,198.796) A22(-91.199,197.796) A23(-90.074,196.796) A24(-91.199,195.796) A25(-90.074,194.796) A26(-91.199,193.796) A27(-90.074,192.796) A28(-91.199,191.796) A29(-90.074,190.796) A30(-91.199,189.796) A31(-90.074,188.796) A32(-91.199,187.796) A33(-90.074,186.796) A34(-91.199,185.796) A35(-90.074,184.796) A36(-91.199,183.796) A37(-90.074,182.796) A38(-91.199,181.796) A39(-90.074,180.796) A40(-91.199,179.796) A41(-90.074,178.796) A42(-91.199,177.796) A43(-90.074,176.796) A44(-91.199,175.796) A45(-90.074,174.796) A46(-91.199,173.796) A47(-90.074,172.796) A48(-91.199,171.796) A49(-90.074,170.796) A50(-91.199,169.796) A51(-90.074,168.796) A52(-91.199,167.796) A53(-90.074,166.796) A54(-91.199,165.796) A55(-90.074,164.796) A56(-91.199,163.796) A57(-90.074,162.796) A58(-91.199,161.796) A59(-90.074,160.796) A60(-91.199,159.796) A61(-90.074,158.796) B2(-88.95,217.796) B3(-87.825,216.796) B4(-88.95,215.796) B5(-87.825,214.796) B6(-88.95,213.796) B7(-87.825,212.796) B8(-88.95,211.796) B9(-87.825,210.796) B10(-88.95,209.796) B11(-87.825,208.796) B12(-88.95,207.796) B13(-87.825,206.796) B14(-88.95,205.796) B15(-87.825,204.796) B16(-88.95,203.796) B17(-87.825,202.796) B18(-88.95,201.796) B19(-87.825,200.796) B20(-88.95,199.796) B21(-87.825,198.796) B22(-88.95,197.796) B23(-87.825,196.796) B24(-88.95,195.796) B25(-87.825,194.796) B26(-88.95,193.796) B27(-87.825,192.796) B28(-88.95,191.796) B29(-87.825,190.796) B30(-88.95,189.796) B31(-87.825,188.796) B32(-88.95,187.796) B33(-87.825,186.796) B34(-88.95,185.796) B35(-87.825,184.796) B36(-88.95,183.796) B37(-87.825,182.796) B38(-88.95,181.796) B39(-87.825,180.796) B40(-88.95,179.796) B41(-87.825,178.796) B42(-88.95,177.796) B43(-87.825,176.796) B44(-88.95,175.796) B45(-87.825,174.796) B46(-88.95,173.796) B47(-87.825,172.796) B48(-88.95,171.796) B49(-87.825,170.796) B50(-88.95,169.796) B51(-87.825,168.796) B52(-88.95,167.796) B53(-87.825,166.796) B54(-88.95,165.796) B55(-87.825,164.796) B56(-88.95,163.796) B57(-87.825,162.796) B58(-88.95,161.796) B59(-87.825,160.796) B60(-88.95,159.796) B61(-87.825,158.796) C2(-86.7,217.796) C3(-85.574,216.796) C4(-86.7,215.796) C5(-85.574,214.796) C6(-86.7,213.796) C7(-85.574,212.796) C8(-86.7,211.796) C9(-85.574,210.796) C10(-86.7,209.796) C11(-85.574,208.796) C12(-86.7,207.796) C13(-85.574,206.796) C14(-86.7,205.796) C15(-85.574,204.796) C16(-86.7,203.796) C17(-85.574,202.796) C18(-86.7,201.796) C19(-85.574,200.796) C20(-86.7,199.796) C21(-85.574,198.796) C22(-86.7,197.796) C23(-85.574,196.796) C24(-86.7,195.796) C25(-85.574,194.796) C26(-86.7,193.796) C27(-85.574,192.796) C28(-86.7,191.796) C29(-85.574,190.796) C30(-86.7,189.796) C31(-85.574,188.796) C32(-86.7,187.796) C33(-85.574,186.796) C34(-86.7,185.796) C35(-85.574,184.796) C36(-86.7,183.796) C37(-85.574,182.796) C38(-86.7,181.796) C39(-85.574,180.796) C40(-86.7,179.796) C41(-85.574,178.796) C42(-86.7,177.796) C43(-85.574,176.796) C44(-86.7,175.796) C45(-85.574,174.796) C46(-86.7,173.796) C47(-85.574,172.796) C48(-86.7,171.796) C49(-85.574,170.796) C50(-86.7,169.796) C51(-85.574,168.796) C52(-86.7,167.796) C53(-85.574,166.796) C54(-86.7,165.796) C55(-85.574,164.796) C56(-86.7,163.796) C57(-85.574,162.796) C58(-86.7,161.796) C59(-85.574,160.796) C60(-86.7,159.796) C61(-85.574,158.796) D2(-84.449,217.796) D3(-83.324,216.796) D4(-84.449,215.796) D5(-83.324,214.796) D6(-84.449,213.796) D7(-83.324,212.796) D8(-84.449,211.796) D9(-83.324,210.796) D10(-84.449,209.796) D11(-83.324,208.796) D12(-84.449,207.796) D13(-83.324,206.796) D14(-84.449,205.796) D15(-83.324,204.796) D16(-84.449,203.796) D17(-83.324,202.796) D18(-84.449,201.796) D19(-83.324,200.796) D20(-84.449,199.796) D21(-83.324,198.796) D22(-84.449,197.796) D23(-83.324,196.796) D24(-84.449,195.796) D25(-83.324,194.796) D26(-84.449,193.796) D27(-83.324,192.796) D28(-84.449,191.796) D29(-83.324,190.796) D30(-84.449,189.796) D31(-83.324,188.796) D32(-84.449,187.796) D33(-83.324,186.796) D34(-84.449,185.796) D35(-83.324,184.796) D36(-84.449,183.796) D37(-83.324,182.796) D38(-84.449,181.796) D39(-83.324,180.796) D40(-84.449,179.796) D41(-83.324,178.796) D42(-84.449,177.796) D43(-83.324,176.796) D44(-84.449,175.796) D45(-83.324,174.796) D46(-84.449,173.796) D47(-83.324,172.796) D48(-84.449,171.796) D49(-83.324,170.796) D50(-84.449,169.796) D51(-83.324,168.796) D52(-84.449,167.796) D53(-83.324,166.796) D54(-84.449,165.796) D55(-83.324,164.796) D56(-84.449,163.796) D57(-83.324,162.796) D58(-84.449,161.796) D59(-83.324,160.796) D60(-84.449,159.796) D61(-83.324,158.796) E2(-82.199,217.796) E3(-81.075,216.796) E4(-82.199,215.796) E5(-81.075,214.796) E6(-82.199,213.796) E7(-81.075,212.796) E8(-82.199,211.796) E9(-81.075,210.796) E10(-82.199,209.796) E11(-81.075,208.796) E12(-82.199,207.796) E13(-81.075,206.796) E14(-82.199,205.796) E15(-81.075,204.796) E16(-82.199,203.796) E17(-81.075,202.796) E18(-82.199,201.796) E19(-81.075,200.796) E20(-82.199,199.796) E21(-81.075,198.796) E22(-82.199,197.796) E23(-81.075,196.796) E24(-82.199,195.796) E25(-81.075,194.796) E26(-82.199,193.796) E27(-81.075,192.796) E28(-82.199,191.796) E29(-81.075,190.796) E30(-82.199,189.796) E31(-81.075,188.796) E32(-82.199,187.796) E33(-81.075,186.796) E34(-82.199,185.796) E35(-81.075,184.796) E36(-82.199,183.796) E37(-81.075,182.796) E38(-82.199,181.796) E39(-81.075,180.796) E40(-82.199,179.796) E41(-81.075,178.796) E42(-82.199,177.796) E43(-81.075,176.796) E44(-82.199,175.796) E45(-81.075,174.796) E46(-82.199,173.796) E47(-81.075,172.796) E48(-82.199,171.796) E49(-81.075,170.796) E50(-82.199,169.796) E51(-81.075,168.796) E52(-82.199,167.796) E53(-81.075,166.796) E54(-82.199,165.796) E55(-81.075,164.796) E56(-82.199,163.796) E57(-81.075,162.796) E58(-82.199,161.796) E59(-81.075,160.796) E60(-82.199,159.796) E61(-81.075,158.796) F2(-79.95,217.796) F3(-78.825,216.796) F4(-79.95,215.796) F5(-78.825,214.796) F6(-79.95,213.796) F7(-78.825,212.796) F8(-79.95,211.796) F9(-78.825,210.796) F10(-79.95,209.796) F11(-78.825,208.796) F12(-79.95,207.796) F13(-78.825,206.796) F14(-79.95,205.796) F15(-78.825,204.796) F16(-79.95,203.796) F17(-78.825,202.796) F18(-79.95,201.796) F19(-78.825,200.796) F20(-79.95,199.796) F21(-78.825,198.796) F22(-79.95,197.796) F23(-78.825,196.796) F24(-79.95,195.796) F25(-78.825,194.796) F26(-79.95,193.796) F27(-78.825,192.796) F28(-79.95,191.796) F29(-78.825,190.796) F30(-79.95,189.796) F31(-78.825,188.796) F32(-79.95,187.796) F33(-78.825,186.796) F34(-79.95,185.796) F35(-78.825,184.796) F36(-79.95,183.796) F37(-78.825,182.796) F38(-79.95,181.796) F39(-78.825,180.796) F40(-79.95,179.796) F41(-78.825,178.796) F42(-79.95,177.796) F43(-78.825,176.796) F44(-79.95,175.796) F45(-78.825,174.796) F46(-79.95,173.796) F47(-78.825,172.796) F48(-79.95,171.796) F49(-78.825,170.796) F50(-79.95,169.796) F51(-78.825,168.796) F52(-79.95,167.796) F53(-78.825,166.796) F54(-79.95,165.796) F55(-78.825,164.796) F56(-79.95,163.796) F57(-78.825,162.796) F58(-79.95,161.796) F59(-78.825,160.796) F60(-79.95,159.796) F61(-78.825,158.796) G2(-77.7,217.796) G4(-77.7,215.796) G6(-77.7,213.796) G8(-77.7,211.796) G10(-77.7,209.796) G12(-77.7,207.796) G14(-77.7,205.796) G16(-77.7,203.796) G18(-77.7,201.796) G20(-77.7,199.796) G22(-77.7,197.796) G24(-77.7,195.796) G26(-77.7,193.796) G28(-77.7,191.796) G30(-77.7,189.796) G32(-77.7,187.796) G34(-77.7,185.796) G36(-77.7,183.796) G38(-77.7,181.796) G40(-77.7,179.796) Z5(-92.324,214.796) Z7(-92.324,212.796) Z9(-92.324,210.796) Z11(-92.324,208.796) Z13(-92.324,206.796) Z15(-92.324,204.796) Z17(-92.324,202.796) Z19(-92.324,200.796) Z21(-92.324,198.796) Z23(-92.324,196.796) Z25(-92.324,194.796) Z27(-92.324,192.796) Z29(-92.324,190.796) Z31(-92.324,188.796) Z33(-92.324,186.796) Z35(-92.324,184.796) Z37(-92.324,182.796) Z39(-92.324,180.796) Z41(-92.324,178.796) Z43(-92.324,176.796) Z45(-92.324,174.796) Z47(-92.324,172.796) Z49(-92.324,170.796) Z51(-92.324,168.796) Z53(-92.324,166.796) Z55(-92.324,164.796) Z57(-92.324,162.796) Z59(-92.324,160.796) Z61(-92.324,158.796)
  round 1.016 smd: B1(-87.825,218.796) B62(-88.95,157.796) C1(-85.574,218.796) C62(-86.7,157.796) D1(-83.324,218.796) E1(-81.075,218.796) E62(-82.199,157.796) F1(-78.825,218.796) F62(-79.95,157.796) G42(-77.7,177.796) G44(-77.7,175.796) G46(-77.7,173.796) G48(-77.7,171.796) G50(-77.7,169.796) G52(-77.7,167.796) G54(-77.7,165.796) G56(-77.7,163.796) G58(-77.7,161.796) G60(-77.7,159.796)
PG_LTXDX_F_X1_GX1X_SL04
  round 0.051 hole 2.489x2.21 unplated: (-60.335,-220.342)
  round 0.508 hole 3.2 unplated: (-59.335,-154.842)
  rect 1.016x1.016 smd: A1(-54.706,-218.796)
  round 1.016 hole 0.559: A2(-53.58,-217.796) A3(-54.706,-216.796) A4(-53.58,-215.796) A5(-54.706,-214.796) A6(-53.58,-213.796) A7(-54.706,-212.796) A8(-53.58,-211.796) A9(-54.706,-210.796) A10(-53.58,-209.796) A11(-54.706,-208.796) A12(-53.58,-207.796) A13(-54.706,-206.796) A14(-53.58,-205.796) A15(-54.706,-204.796) A16(-53.58,-203.796) A17(-54.706,-202.796) A18(-53.58,-201.796) A19(-54.706,-200.796) A20(-53.58,-199.796) A21(-54.706,-198.796) A22(-53.58,-197.796) A23(-54.706,-196.796) A24(-53.58,-195.796) A25(-54.706,-194.796) A26(-53.58,-193.796) A27(-54.706,-192.796) A28(-53.58,-191.796) A29(-54.706,-190.796) A30(-53.58,-189.796) A31(-54.706,-188.796) A32(-53.58,-187.796) A33(-54.706,-186.796) A34(-53.58,-185.796) A35(-54.706,-184.796) A36(-53.58,-183.796) A37(-54.706,-182.796) A38(-53.58,-181.796) A39(-54.706,-180.796) A40(-53.58,-179.796) A41(-54.706,-178.796) A42(-53.58,-177.796) A43(-54.706,-176.796) A44(-53.58,-175.796) A45(-54.706,-174.796) A46(-53.58,-173.796) A47(-54.706,-172.796) A48(-53.58,-171.796) A49(-54.706,-170.796) A50(-53.58,-169.796) A51(-54.706,-168.796) A52(-53.58,-167.796) A53(-54.706,-166.796) A54(-53.58,-165.796) A55(-54.706,-164.796) A56(-53.58,-163.796) A57(-54.706,-162.796) A58(-53.58,-161.796) A59(-54.706,-160.796) A60(-53.58,-159.796) A61(-54.706,-158.796) B2(-55.829,-217.796) B3(-56.954,-216.796) B4(-55.829,-215.796) B5(-56.954,-214.796) B6(-55.829,-213.796) B7(-56.954,-212.796) B8(-55.829,-211.796) B9(-56.954,-210.796) B10(-55.829,-209.796) B11(-56.954,-208.796) B12(-55.829,-207.796) B13(-56.954,-206.796) B14(-55.829,-205.796) B15(-56.954,-204.796) B16(-55.829,-203.796) B17(-56.954,-202.796) B18(-55.829,-201.796) B19(-56.954,-200.796) B20(-55.829,-199.796) B21(-56.954,-198.796) B22(-55.829,-197.796) B23(-56.954,-196.796) B24(-55.829,-195.796) B25(-56.954,-194.796) B26(-55.829,-193.796) B27(-56.954,-192.796) B28(-55.829,-191.796) B29(-56.954,-190.796) B30(-55.829,-189.796) B31(-56.954,-188.796) B32(-55.829,-187.796) B33(-56.954,-186.796) B34(-55.829,-185.796) B35(-56.954,-184.796) B36(-55.829,-183.796) B37(-56.954,-182.796) B38(-55.829,-181.796) B39(-56.954,-180.796) B40(-55.829,-179.796) B41(-56.954,-178.796) B42(-55.829,-177.796) B43(-56.954,-176.796) B44(-55.829,-175.796) B45(-56.954,-174.796) B46(-55.829,-173.796) B47(-56.954,-172.796) B48(-55.829,-171.796) B49(-56.954,-170.796) B50(-55.829,-169.796) B51(-56.954,-168.796) B52(-55.829,-167.796) B53(-56.954,-166.796) B54(-55.829,-165.796) B55(-56.954,-164.796) B56(-55.829,-163.796) B57(-56.954,-162.796) B58(-55.829,-161.796) B59(-56.954,-160.796) B60(-55.829,-159.796) B61(-56.954,-158.796) C2(-58.079,-217.796) C3(-59.205,-216.796) C4(-58.079,-215.796) C5(-59.205,-214.796) C6(-58.079,-213.796) C7(-59.205,-212.796) C8(-58.079,-211.796) C9(-59.205,-210.796) C10(-58.079,-209.796) C11(-59.205,-208.796) C12(-58.079,-207.796) C13(-59.205,-206.796) C14(-58.079,-205.796) C15(-59.205,-204.796) C16(-58.079,-203.796) C17(-59.205,-202.796) C18(-58.079,-201.796) C19(-59.205,-200.796) C20(-58.079,-199.796) C21(-59.205,-198.796) C22(-58.079,-197.796) C23(-59.205,-196.796) C24(-58.079,-195.796) C25(-59.205,-194.796) C26(-58.079,-193.796) C27(-59.205,-192.796) C28(-58.079,-191.796) C29(-59.205,-190.796) C30(-58.079,-189.796) C31(-59.205,-188.796) C32(-58.079,-187.796) C33(-59.205,-186.796) C34(-58.079,-185.796) C35(-59.205,-184.796) C36(-58.079,-183.796) C37(-59.205,-182.796) C38(-58.079,-181.796) C39(-59.205,-180.796) C40(-58.079,-179.796) C41(-59.205,-178.796) C42(-58.079,-177.796) C43(-59.205,-176.796) C44(-58.079,-175.796) C45(-59.205,-174.796) C46(-58.079,-173.796) C47(-59.205,-172.796) C48(-58.079,-171.796) C49(-59.205,-170.796) C50(-58.079,-169.796) C51(-59.205,-168.796) C52(-58.079,-167.796) C53(-59.205,-166.796) C54(-58.079,-165.796) C55(-59.205,-164.796) C56(-58.079,-163.796) C57(-59.205,-162.796) C58(-58.079,-161.796) C59(-59.205,-160.796) C60(-58.079,-159.796) C61(-59.205,-158.796) D2(-60.33,-217.796) D3(-61.455,-216.796) D4(-60.33,-215.796) D5(-61.455,-214.796) D6(-60.33,-213.796) D7(-61.455,-212.796) D8(-60.33,-211.796) D9(-61.455,-210.796) D10(-60.33,-209.796) D11(-61.455,-208.796) D12(-60.33,-207.796) D13(-61.455,-206.796) D14(-60.33,-205.796) D15(-61.455,-204.796) D16(-60.33,-203.796) D17(-61.455,-202.796) D18(-60.33,-201.796) D19(-61.455,-200.796) D20(-60.33,-199.796) D21(-61.455,-198.796) D22(-60.33,-197.796) D23(-61.455,-196.796) D24(-60.33,-195.796) D25(-61.455,-194.796) D26(-60.33,-193.796) D27(-61.455,-192.796) D28(-60.33,-191.796) D29(-61.455,-190.796) D30(-60.33,-189.796) D31(-61.455,-188.796) D32(-60.33,-187.796) D33(-61.455,-186.796) D34(-60.33,-185.796) D35(-61.455,-184.796) D36(-60.33,-183.796) D37(-61.455,-182.796) D38(-60.33,-181.796) D39(-61.455,-180.796) D40(-60.33,-179.796) D41(-61.455,-178.796) D42(-60.33,-177.796) D43(-61.455,-176.796) D44(-60.33,-175.796) D45(-61.455,-174.796) D46(-60.33,-173.796) D47(-61.455,-172.796) D48(-60.33,-171.796) D49(-61.455,-170.796) D50(-60.33,-169.796) D51(-61.455,-168.796) D52(-60.33,-167.796) D53(-61.455,-166.796) D54(-60.33,-165.796) D55(-61.455,-164.796) D56(-60.33,-163.796) D57(-61.455,-162.796) D58(-60.33,-161.796) D59(-61.455,-160.796) D60(-60.33,-159.796) D61(-61.455,-158.796) E2(-62.58,-217.796) E3(-63.705,-216.796) E4(-62.58,-215.796) E5(-63.704,-214.796) E6(-62.58,-213.796) E7(-63.704,-212.796) E8(-62.58,-211.796) E9(-63.704,-210.796) E10(-62.58,-209.796) E11(-63.704,-208.796) E12(-62.58,-207.796) E13(-63.704,-206.796) E14(-62.58,-205.796) E15(-63.704,-204.796) E16(-62.58,-203.796) E17(-63.704,-202.796) E18(-62.58,-201.796) E19(-63.704,-200.796) E20(-62.58,-199.796) E21(-63.704,-198.796) E22(-62.58,-197.796) E23(-63.704,-196.796) E24(-62.58,-195.796) E25(-63.704,-194.796) E26(-62.58,-193.796) E27(-63.704,-192.796) E28(-62.58,-191.796) E29(-63.704,-190.796) E30(-62.58,-189.796) E31(-63.704,-188.796) E32(-62.58,-187.796) E33(-63.704,-186.796) E34(-62.58,-185.796) E35(-63.704,-184.796) E36(-62.58,-183.796) E37(-63.704,-182.796) E38(-62.58,-181.796) E39(-63.704,-180.796) E40(-62.58,-179.796) E41(-63.704,-178.796) E42(-62.58,-177.796) E43(-63.704,-176.796) E44(-62.58,-175.796) E45(-63.704,-174.796) E46(-62.58,-173.796) E47(-63.704,-172.796) E48(-62.58,-171.796) E49(-63.704,-170.796) E50(-62.58,-169.796) E51(-63.704,-168.796) E52(-62.58,-167.796) E53(-63.704,-166.796) E54(-62.58,-165.796) E55(-63.704,-164.796) E56(-62.58,-163.796) E57(-63.704,-162.796) E58(-62.58,-161.796) E59(-63.704,-160.796) E60(-62.58,-159.796) E61(-63.704,-158.796) F2(-64.829,-217.796) F3(-65.954,-216.796) F4(-64.829,-215.796) F5(-65.955,-214.796) F6(-64.829,-213.796) F7(-65.955,-212.796) F8(-64.829,-211.796) F9(-65.955,-210.796) F10(-64.829,-209.796) F11(-65.955,-208.796) F12(-64.829,-207.796) F13(-65.955,-206.796) F14(-64.829,-205.796) F15(-65.955,-204.796) F16(-64.829,-203.796) F17(-65.955,-202.796) F18(-64.829,-201.796) F19(-65.955,-200.796) F20(-64.829,-199.796) F21(-65.955,-198.796) F22(-64.829,-197.796) F23(-65.955,-196.796) F24(-64.829,-195.796) F25(-65.955,-194.796) F26(-64.829,-193.796) F27(-65.955,-192.796) F28(-64.829,-191.796) F29(-65.955,-190.796) F30(-64.829,-189.796) F31(-65.955,-188.796) F32(-64.829,-187.796) F33(-65.955,-186.796) F34(-64.829,-185.796) F35(-65.955,-184.796) F36(-64.829,-183.796) F37(-65.955,-182.796) F38(-64.829,-181.796) F39(-65.955,-180.796) F40(-64.829,-179.796) F41(-65.955,-178.796) F42(-64.829,-177.796) F43(-65.955,-176.796) F44(-64.829,-175.796) F45(-65.955,-174.796) F46(-64.829,-173.796) F47(-65.955,-172.796) F48(-64.829,-171.796) F49(-65.955,-170.796) F50(-64.829,-169.796) F51(-65.955,-168.796) F52(-64.829,-167.796) F53(-65.955,-166.796) F54(-64.829,-165.796) F55(-65.955,-164.796) F56(-64.829,-163.796) F57(-65.955,-162.796) F58(-64.829,-161.796) F59(-65.955,-160.796) F60(-64.829,-159.796) F61(-65.955,-158.796) G2(-67.08,-217.796) G4(-67.08,-215.796) G6(-67.08,-213.796) G8(-67.08,-211.796) G10(-67.08,-209.796) G12(-67.08,-207.796) G14(-67.08,-205.796) G16(-67.08,-203.796) G18(-67.08,-201.796) G20(-67.08,-199.796) G22(-67.08,-197.796) G24(-67.08,-195.796) G26(-67.08,-193.796) G28(-67.08,-191.796) G30(-67.08,-189.796) G32(-67.08,-187.796) G34(-67.08,-185.796) G36(-67.08,-183.796) G38(-67.08,-181.796) G40(-67.08,-179.796) Z5(-52.456,-214.796) Z7(-52.456,-212.796) Z9(-52.456,-210.796) Z11(-52.456,-208.796) Z13(-52.456,-206.796) Z15(-52.456,-204.796) Z17(-52.456,-202.796) Z19(-52.456,-200.796) Z21(-52.456,-198.796) Z23(-52.456,-196.796) Z25(-52.456,-194.796) Z27(-52.456,-192.796) Z29(-52.456,-190.796) Z31(-52.456,-188.796) Z33(-52.456,-186.796) Z35(-52.456,-184.796) Z37(-52.456,-182.796) Z39(-52.456,-180.796) Z41(-52.456,-178.796) Z43(-52.456,-176.796) Z45(-52.456,-174.796) Z47(-52.456,-172.796) Z49(-52.456,-170.796) Z51(-52.456,-168.796) Z53(-52.456,-166.796) Z55(-52.456,-164.796) Z57(-52.456,-162.796) Z59(-52.456,-160.796) Z61(-52.456,-158.796)
  round 1.016 smd: B1(-56.954,-218.796) B62(-55.829,-157.796) C1(-59.206,-218.796) C62(-58.079,-157.796) D1(-61.456,-218.796) E1(-63.705,-218.796) E62(-62.58,-157.796) F1(-65.954,-218.796) F62(-64.829,-157.796) G42(-67.08,-177.796) G44(-67.08,-175.796) G46(-67.08,-173.796) G48(-67.08,-171.796) G50(-67.08,-169.796) G52(-67.08,-167.796) G54(-67.08,-165.796) G56(-67.08,-163.796) G58(-67.08,-161.796) G60(-67.08,-159.796)
